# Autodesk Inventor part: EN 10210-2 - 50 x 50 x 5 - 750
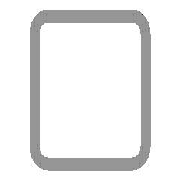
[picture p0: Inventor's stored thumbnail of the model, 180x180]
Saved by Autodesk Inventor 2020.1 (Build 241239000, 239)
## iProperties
Created: 2019-01
Part Number: EN 10210-2 - 50 x 50 x 5 - 750
Material: Stahl, weich
Description: Rohrleitung
Document SubType Name: Modeling
Standard: DIN EN 10210-2
Designer: lutzd
Standard Revision: 2006-07
Standards Organization: DIN
Language: de-DE
Size Designation: 50 x 50 x 5
Categories: <MemberInstance><Categories><Category DisplayName="Profile" InternalName="089c4875-fa83-4c05-b084-43b9cc11f5ed" Mnemonic="GRDR"><CategoryParameter DisplayName="
Stock Number: 50 x 50 x 5
Mass: 5134.01 g
Surface Area: 2558.26 cm^2
Volume: 654.014 cm^3
Density: 7.85 g/cm^3
Appearance: Semi-Polished(8)
_CCFamilyMember: 16
_CCFamilyDisplayName: DIN EN 10210-2 (USAS B17.1 quadratisch) - Rohrleitung — In Klammern angegebene Größen wurden aufgehoben
_FrameMemberDoc: Frame Member File
_Version: 15.0.0
_GetPNFromCC: 1
IsCustomPart: 1
G_W: 50,000 mm
G_H: 50,000 mm
G_L: 750,000 mm
DocNumber: ADSK-014328
Folder: .
Dimensions: 50x50x750 mm
Mass: 5,134 kg
VLT_Material: Stahl, weich
Title: Profil-Bauteil
Author: lutzd
Revision Number: -
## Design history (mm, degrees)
node "Startebene"
node "Endebene"
sketch "Skizze"
  geometry: L1 (-25, -17.5)-(-25, 17.5); L2 (-17.5, 25)-(17.5, 25); L3 (25, 17.5)-(25, -17.5); L4 (17.5, -25)-(-17.5, -25); L5 (-15, 20)-(15, 20); L6 (20, 15)-(20, -15); L7 (15, -20)-(-15, -20); L8 (-20, -15)-(-20, 15); L9 (0, 37.175)-(0, -37.175) reference; L10 (-37.175, 0)-(37.175, 0) reference; A1 r 7.5 centre (-17.5, -17.5) between (-25, -17.5) and (-17.5, -25); A2 r 7.5 centre (-17.5, 17.5) between (-17.5, 25) and (-25, 17.5); A3 r 7.5 centre (17.5, 17.5) between (25, 17.5) and (17.5, 25); A4 r 7.5 centre (17.5, -17.5) between (17.5, -25) and (25, -17.5); A5 r 5 centre (-15, -15) between (-20, -15) and (-15, -20); A6 r 5 centre (-15, 15) between (-15, 20) and (-20, 15); A7 r 5 centre (15, 15) between (20, 15) and (15, 20); A8 r 5 centre (15, -15) between (15, -20) and (20, -15)
  constraints: 16 end point, 16 point on circle, 16 tangent, 8 centre point, 6 equal radius, 4 parallel, 2 perpendicular, 2 other
  dimensions: "d7" = 7.5 radius of A1 (= G_IR); "d10" = 50 distance between parallel lines of L2 L4 (= G_H); "d11" = 50 distance between parallel lines of L1 L3 (= G_W); "d12" = 5 distance between parallel lines of L3 L6 (= G_T); "d15" = 25 distance between parallel lines of L2 L10 (= 0.5 x d10); "d16" = 25 distance between parallel lines of L9 L3 (= 0.5 x d11); "d19" = 5 radius of A5 (= G_T); "d20" = 5 distance between parallel lines of L4 L7 (= G_T)
extrude "Körper" new body sketch "Skizze" stored distance "d3" = 750 (= G_L); taper "d4" = 0 deg
node "Driven Length"
  sketch "Sketch3"
    geometry: L1 (0, 0)-(10, 0) reference
    constraints: 2 end point, 1 horizontal
  workplane "Work Plane3"
  sketch "Sketch4"
    geometry: L1 (-2, 0)-(12, 0) reference; L2 (-2, 750)-(12, 750) reference
    dimensions: "d18" = 750 distance between parallel lines of L1 L2 (derived)
sketch "Skizze5"
  geometry: L1 (750, 35)-(750, 0) reference; L2 (750, 17.5)-(581, 17.5); 2 further points
  constraints: 2 end point, 1 coincident, 1 horizontal, 1 point on line
  dimensions: "d21" = 38 distance of point (581, 17.5) point (619, 17.5); "d22" = 131 distance from line of L1 point (619, 17.5)
hole "Bohrung1" sketch "Skizze5" at (581, 17.5), (619, 17.5) diameter "d23" = 6.647; stored, may be unused: countersink angle "d27" = 90 deg, drill point angle "d29" = 118 deg; dims "d24" = 16, "d25" = 4, "d26" = 2, "d28" = 8
sketch "Skizze6"
  geometry: L1 (35, 0)-(0, 0) reference; L2 (17.5, 0)-(17.5, 52.35); 2 further points
  constraints: 2 end point, 1 coincident, 1 point on line, 1 vertical
  dimensions: "d30" = 14.35 distance from line of L1 point (17.5, 14.35); "d31" = 38 distance of L2.end point (17.5, 14.35)
hole "Bohrung2" sketch "Skizze6" at (17.5, 14.35), (17.5, 52.35) diameter "d32" = 6.647; stored, may be unused: countersink angle "d36" = 90 deg, drill point angle "d38" = 118 deg; dims "d33" = 16, "d34" = 4, "d35" = 2, "d37" = 8
sketch "Skizze7"
  geometry: L1 (0, -17.5)-(303, -17.5); 1 further point
  constraints: 2 end point, 1 coincident, 1 horizontal
  dimensions: "d39" = 303 distance of L1.start L1.end
hole "Bohrung3" sketch "Skizze7" at (303, -17.5) diameter "d40" = 6.647; stored, may be unused: countersink angle "d44" = 90 deg, drill point angle "d46" = 118 deg; dims "d41" = 16, "d42" = 4, "d43" = 2, "d45" = 8
body "Solid1"
other parameters: "G_W" = 50 [user parameter; used in 1 equation term], "G_H" = 50 [user parameter; used in 1 equation term], "G_T" = 5 [user parameter; used in 3 equation terms], "G_IR" = 7.5 [user parameter; used in 1 equation term], "G_L" = 750 (= d18) [user parameter; used in 1 equation term], "G_OFFSET_START" = 0 [user parameter; used in 1 equation term], "G_OFFSET_END" = 0 [user parameter; used in 1 equation term], "d13" = 0 (computed from G_OFFSET_START), "d17" = 90 deg
